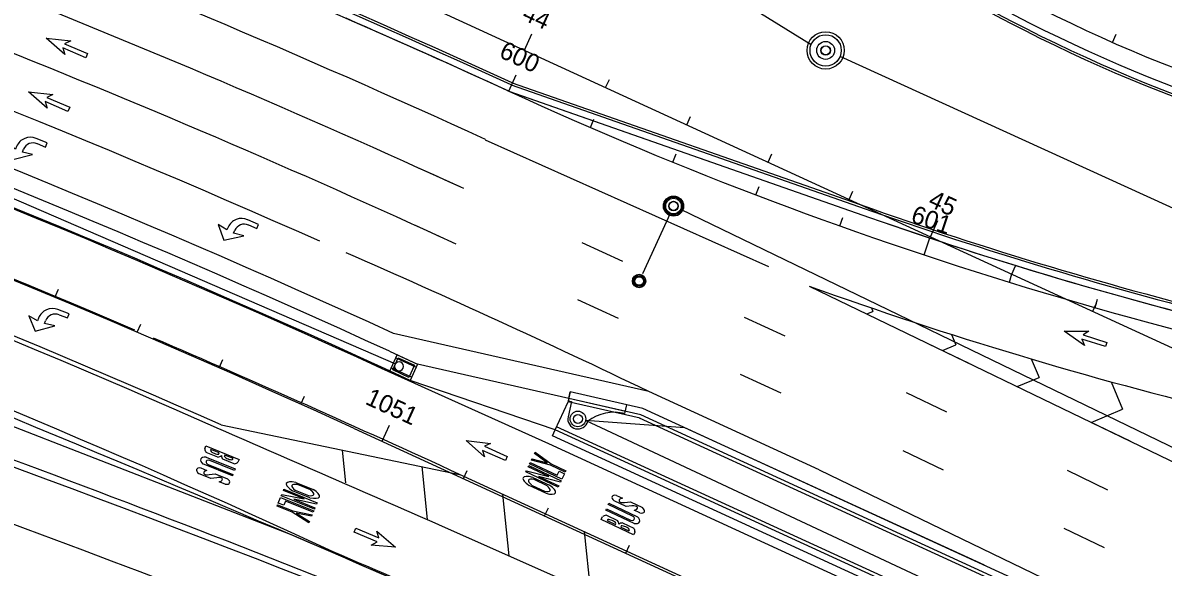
# Model space of a CAD drawing. Extents: x 468143 to 491361, y 1438528 to 1468730.
# Drawn here: x 487342.4 to 487597.7, y 1467252.2 to 1467373.9 of the extents above; entities that cross this region are included whole.
import ezdxf

# ---------------------------------------------------------------- set-up
doc = ezdxf.new("R2010")
doc.units = 0
doc.layers.add('Default', color=7, linetype='Continuous')
doc.layers.add('Xreference_dp', color=7, linetype='Continuous')

# ---------------------------------------------------------------- blocks, each defined once
blk = doc.blocks.new('POINT_DISPLAY')
at = {"layer": 'Default'}
blk.add_line((0, 0), (0, 0), dxfattribs=at)
blk = doc.blocks.new('InltCurb1_35')
at = {"layer": 'Default'}
for p, q in [((2.25, 2), (2.25, 5.5)), ((-10, 2), (-10, 0)), ((-10, 1.5), (3, 1.5)), ((3, 2), (2.25, 2)), ((3, 0), (3, 2))]:
    blk.add_line(p, q, dxfattribs=at)
for radius in [1.75, 1]:
    blk.add_circle((0, 5.5), radius, dxfattribs=at)
for centre, radius, start, end in [((0, 5.5), 2.25, 0, 180), ((-9.85, 12), 10, 269.1432, 319.4677)]:
    blk.add_arc(centre, radius, start, end, dxfattribs=at)
for p in [(0, 7.75), (-1.75, 5.5), (-1.75, 5.5), (-1.6, 6.2), (-1.22, 6.76), (-0.66, 7.12), (0, 7.25), (0, 7.25), (0, 5.5), (0, 5.5), (0.7, 7.1), (1.26, 6.72), (1.62, 6.16), (1.75, 5.5), (1.75, 5.5), (-1.62, 4.84), (-1.26, 4.28), (-0.7, 3.9), (0, 3.75), (0, 3.75), (0.66, 3.88), (1.22, 4.24), (1.6, 4.8), (0, 0), (0, 0)]:
    blk.add_blockref('POINT_DISPLAY', p, dxfattribs=at)
blk = doc.blocks.new('InltCurb7_40')
at = {"layer": 'Default'}
for p, q in [((2.5, 4), (-2.5, 4)), ((-2.5, 4), (-2.5, 0)), ((2.5, 3.25), (-2.5, 3.25)), ((2.5, 0), (2.5, 4)), ((-2.5, 0.75), (2.5, 0.75)), ((-2.5, 0), (2.5, 0))]:
    blk.add_line(p, q, dxfattribs=at)
blk.add_lwpolyline([(-2, 0.5), (2, 0.5), (2, 3.5), (-2, 3.5)], close=True, dxfattribs=at)
blk.add_circle((-1.04, 2.19), 1, dxfattribs=at)
for p in [(-2, 3.5), (0, 4), (0, 3.5), (0, 3.5), (2, 3.5), (-2, 2), (-2, 2), (-2, 0.5), (0, 2), (0, 2), (0, 0.5), (0, 0.5), (0, 0), (0, 0), (2, 2), (2, 2), (2, 0.5)]:
    blk.add_blockref('POINT_DISPLAY', p, dxfattribs=at)
blk = doc.blocks.new('MH2')
at = {"layer": 'Default'}
for p, q in [((-1.25, 0.03), (-1.05, 0.03)), ((-0.9, 0.87), (-0.76, 0.73)), ((-0.87, 0.9), (-0.73, 0.76)), ((-0.03, 1.25), (-0.03, 1.05)), ((0.03, 1.25), (0.03, 1.05)), ((0.87, 0.9), (0.73, 0.76)), ((0.9, 0.87), (0.76, 0.73)), ((1.05, 0.03), (1.25, 0.03)), ((-1.25, -0.03), (-1.05, -0.03)), ((-0.76, -0.73), (-0.9, -0.87)), ((-0.73, -0.76), (-0.87, -0.9)), ((-0.03, -1.05), (-0.03, -1.25)), ((0.03, -1.05), (0.03, -1.25)), ((0.73, -0.76), (0.87, -0.9)), ((0.76, -0.73), (0.9, -0.87)), ((1.05, -0.03), (1.25, -0.03))]:
    blk.add_line(p, q, dxfattribs=at)
for radius in [1.5, 1.25, 1.05, 1, 0.958]:
    blk.add_circle((0, 0), radius, dxfattribs=at)
for p in [(-1, 0), (-0.71, 0.71), (0, 1.5), (0, 1), (0, 0), (0, 0), (0, 0), (0.71, 0.71), (1, 0), (-0.71, -0.71), (0, -1), (0, -1.5), (0.71, -0.71)]:
    blk.add_blockref('POINT_DISPLAY', p, dxfattribs=at)
blk = doc.blocks.new('MHCover2')
at = {"layer": 'Default'}
for radius in [2, 1.06, 1]:
    blk.add_circle((0, 0), radius, dxfattribs=at)
for p in [(-2, 0), (-2, 0), (-1.83, 0.81), (-1.39, 1.43), (-0.75, 1.85), (0, 2.5), (0, 2), (0, 2), (0, 0), (0, 0), (0, 0), (0.81, 1.83), (1.43, 1.39), (1.85, 0.75), (2, 0), (2, 0), (-1.85, -0.75), (-1.43, -1.39), (-0.81, -1.83), (0, -2), (0, -2), (0, -2.5), (0.75, -1.85), (1.39, -1.43), (1.83, -0.81)]:
    blk.add_blockref('POINT_DISPLAY', p, dxfattribs=at)
blk = doc.blocks.new('JBottom70Dia')
at = {"layer": 'Default'}
for radius in [4.17, 3.5, 3.5]:
    blk.add_circle((0, 0), radius, dxfattribs=at)
for p in [(-1.32, 3.24), (0, 3.5), (0, 3.5), (0, 3.5), (1.41, 3.2), (-3.5, 0), (-3.5, 0), (-3.2, 1.41), (-2.44, 2.51), (0, 0), (0, 0), (0, 0), (2.51, 2.44), (3.24, 1.32), (-3.24, -1.32), (-2.51, -2.44), (2.44, -2.51), (3.2, -1.41), (3.5, 0), (3.5, 0), (-1.41, -3.2), (0, -3.5), (0, -3.5), (0, -3.5), (1.32, -3.24)]:
    blk.add_blockref('POINT_DISPLAY', p, dxfattribs=at)
blk = doc.blocks.new('PBottom35Dia')
at = {"layer": 'Default'}
for radius in [2.25, 1.75, 1.75]:
    blk.add_circle((0, 0), radius, dxfattribs=at)
for p in [(-1.75, 0), (-1.75, 0), (-1.6, 0.7), (-1.22, 1.26), (-0.66, 1.62), (0, 1.75), (0, 1.75), (0, 1.75), (0, 0), (0, 0), (0.7, 1.6), (1.26, 1.22), (1.62, 0.66), (1.75, 0), (1.75, 0), (-1.62, -0.66), (-1.26, -1.22), (-0.7, -1.6), (0, -1.75), (0, -1.75), (0, -1.75), (0.66, -1.62), (1.22, -1.26), (1.6, -0.7)]:
    blk.add_blockref('POINT_DISPLAY', p, dxfattribs=at)
blk = doc.blocks.new('DALeftTurn_1')
at = {"layer": 'Default'}
for points in [[(5.67, 3.17), (2, 0.5), (4.33, 0.83), (4.33, 0.17)], [(6, 0.17), (6, 0.83), (8.25, 0.5), (5.67, 3.17)], [(2, -2.17), (0, -2.17), (0, -3.17), (2.67, -3.17)]]:
    blk.add_lwpolyline(points, dxfattribs=at)
for centre, radius in [((2, 0.17), 2.33), ((2.67, 0.17), 3.33)]:
    blk.add_arc(centre, radius, 270, 0, dxfattribs=at)
blk = doc.blocks.new('DAMerge_2')
at = {"layer": 'Default'}
blk.add_lwpolyline([(0.71, -4.09), (0, -3.39), (3.95, 0.56), (2.42, 0.68), (7.31, 3.21), (4.77, -1.68), (4.66, -0.15), (0.71, -4.09)], dxfattribs=at)
blk = doc.blocks.new('BUS_7')
at = {"layer": 'Default'}
for p, q in [((0, 2.46), (0, 3.17)), ((0, 3.17), (8, 3.17)), ((3.33, 2.83), (1.33, 2.83)), ((1.33, 2.83), (1.33, 2.58)), ((3.33, 2.58), (3.33, 2.83)), ((6.67, 2.83), (4.67, 2.83)), ((4.67, 2.83), (4.67, 2.58)), ((6.67, 2.58), (6.67, 2.83)), ((8, 3.17), (8, 2.46)), ((3.38, 1.83), (0.62, 1.83)), ((0.97, 0.86), (8, 0.86)), ((8, 0.5), (2, 0.5)), ((7.38, 1.83), (4.62, 1.83)), ((8, 0.86), (8, 0.5)), ((0.8, -1.83), (2.26, -1.83)), ((8, -0.83), (0.89, -0.83)), ((2, -0.5), (8, -0.5)), ((3.08, -2.5), (4.23, -1.83)), ((4.93, -2.5), (3.77, -3.17)), ((4.23, -1.83), (7.2, -1.83)), ((8, -0.5), (8, -0.83)), ((3.77, -3.17), (0.8, -3.17)), ((7.2, -3.17), (5.74, -3.17))]:
    blk.add_line(p, q, dxfattribs=at)
for centre, major_axis, ratio, start_param, end_param in [((2.33, 2.83), (-1.17, 0), 0.428571, 0.5411, 2.600493), ((5.67, 2.83), (1.17, 0), 0.428571, 3.682692, 5.742086), ((2, 0), (2, 0), 0.5, 2.110653, 4.126703), ((2, 2.83), (-2.08, 0), 0.64, 0.283794, 0.848062), ((2, 0), (0.667, 0), 0.75, 1.570796, 4.712389), ((2, 2.83), (-2.08, 0), 0.64, 2.293531, 2.857799), ((6, 2.83), (2.08, 0), 0.64, 3.425387, 3.989655), ((6, 2.83), (2.08, 0), 0.64, 5.435123, 5.999391), ((2, -2.5), (-2, 0), 0.416667, 5.35589, 7.210481), ((2.67, -2.17), (-0.877, -0.48), 0.5, 4.914869, 8.056461), ((5.33, -2.83), (-0.869, -0.495), 0.5, 1.760499, 4.902092), ((6, -2.5), (2, 0), 0.416667, 5.35589, 7.210481)]:
    blk.add_ellipse(centre, major_axis=major_axis, ratio=ratio, start_param=start_param, end_param=end_param, dxfattribs=at)
blk = doc.blocks.new('BikeONLY_2')
at = {"layer": 'Default'}
for p, q in [((0.97, 1.83), (3.03, 1.83)), ((2.8, 1.67), (1.2, 1.67)), ((3.03, 0.83), (0.97, 0.83)), ((1.2, 1), (2.8, 1))]:
    blk.add_line(p, q, dxfattribs=at)
for points in [[(0, -0.17), (0, 0), (2.5, 0.46), (0, 0.46), (0, 0.62), (4, 0.62), (4, 0.46), (1.45, 0), (4, 0), (4, -0.17), (0, -0.17)], [(0.67, -1.04), (0, -1.04), (0, -0.37), (4, -0.37), (4, -0.54), (0.67, -0.54), (0.67, -1.04)], [(4, -1.83), (1.83, -1.42), (0, -1.42), (0, -1.25), (1.83, -1.25), (4, -0.83), (4, -1), (2.28, -1.33), (4, -1.66), (4, -1.83)]]:
    blk.add_lwpolyline(points, dxfattribs=at)
for major_axis, ratio, start_param, end_param in [((2, 0), 0.291667, 2.111896, 4.171289), ((1.33, 0), 0.3125, 2.214297, 4.068888), ((1.33, 0), 0.3125, 5.35589, 7.210481), ((2, 0), 0.291667, 5.253489, 7.312882)]:
    blk.add_ellipse((2, 1.33), major_axis=major_axis, ratio=ratio, start_param=start_param, end_param=end_param, dxfattribs=at)
blk = doc.blocks.new('DALeftTurn_4_1')
at = {"layer": 'Default'}
for points in [[(5.67, 3.17), (2, 0.5), (4.33, 0.83), (4.33, 0.17)], [(6, 0.17), (6, 0.83), (8.25, 0.5), (5.67, 3.17)], [(2, -2.17), (0, -2.17), (0, -3.17), (2.67, -3.17)]]:
    blk.add_lwpolyline(points, dxfattribs=at)
for centre, radius in [((2, 0.17), 2.33), ((2.67, 0.17), 3.33)]:
    blk.add_arc(centre, radius, 270, 0, dxfattribs=at)
blk = doc.blocks.new('DAMerge_6')
at = {"layer": 'Default'}
blk.add_lwpolyline([(0.71, -4.09), (0, -3.39), (3.95, 0.56), (2.42, 0.68), (7.31, 3.21), (4.77, -1.68), (4.66, -0.15), (0.71, -4.09)], dxfattribs=at)
blk = doc.blocks.new('BUS_8')
at = {"layer": 'Default'}
for p, q in [((0, 2.46), (0, 3.17)), ((0, 3.17), (8, 3.17)), ((3.33, 2.83), (1.33, 2.83)), ((1.33, 2.83), (1.33, 2.58)), ((3.33, 2.58), (3.33, 2.83)), ((6.67, 2.83), (4.67, 2.83)), ((4.67, 2.83), (4.67, 2.58)), ((6.67, 2.58), (6.67, 2.83)), ((8, 3.17), (8, 2.46)), ((3.38, 1.83), (0.62, 1.83)), ((0.97, 0.86), (8, 0.86)), ((8, 0.5), (2, 0.5)), ((7.38, 1.83), (4.62, 1.83)), ((8, 0.86), (8, 0.5)), ((0.8, -1.83), (2.26, -1.83)), ((8, -0.83), (0.89, -0.83)), ((2, -0.5), (8, -0.5)), ((3.08, -2.5), (4.23, -1.83)), ((4.93, -2.5), (3.77, -3.17)), ((4.23, -1.83), (7.2, -1.83)), ((8, -0.5), (8, -0.83)), ((3.77, -3.17), (0.8, -3.17)), ((7.2, -3.17), (5.74, -3.17))]:
    blk.add_line(p, q, dxfattribs=at)
for centre, major_axis, ratio, start_param, end_param in [((2.33, 2.83), (-1.17, 0), 0.428571, 0.5411, 2.600493), ((5.67, 2.83), (1.17, 0), 0.428571, 3.682692, 5.742086), ((2, 0), (2, 0), 0.5, 2.110653, 4.126703), ((2, 2.83), (-2.08, 0), 0.64, 0.283794, 0.848062), ((2, 0), (0.667, 0), 0.75, 1.570796, 4.712389), ((2, 2.83), (-2.08, 0), 0.64, 2.293531, 2.857799), ((6, 2.83), (2.08, 0), 0.64, 3.425387, 3.989655), ((6, 2.83), (2.08, 0), 0.64, 5.435123, 5.999391), ((2, -2.5), (-2, 0), 0.416667, 5.35589, 7.210481), ((2.67, -2.17), (-0.877, -0.48), 0.5, 4.914869, 8.056461), ((5.33, -2.83), (-0.869, -0.495), 0.5, 1.760499, 4.902092), ((6, -2.5), (2, 0), 0.416667, 5.35589, 7.210481)]:
    blk.add_ellipse(centre, major_axis=major_axis, ratio=ratio, start_param=start_param, end_param=end_param, dxfattribs=at)
blk = doc.blocks.new('BikeONLY_4')
at = {"layer": 'Default'}
for p, q in [((0.97, 1.83), (3.03, 1.83)), ((2.8, 1.67), (1.2, 1.67)), ((3.03, 0.83), (0.97, 0.83)), ((1.2, 1), (2.8, 1))]:
    blk.add_line(p, q, dxfattribs=at)
for points in [[(0, -0.17), (0, 0), (2.5, 0.46), (0, 0.46), (0, 0.62), (4, 0.62), (4, 0.46), (1.45, 0), (4, 0), (4, -0.17), (0, -0.17)], [(0.67, -1.04), (0, -1.04), (0, -0.37), (4, -0.37), (4, -0.54), (0.67, -0.54), (0.67, -1.04)], [(4, -1.83), (1.83, -1.42), (0, -1.42), (0, -1.25), (1.83, -1.25), (4, -0.83), (4, -1), (2.28, -1.33), (4, -1.66), (4, -1.83)]]:
    blk.add_lwpolyline(points, dxfattribs=at)
for major_axis, ratio, start_param, end_param in [((2, 0), 0.291667, 2.111896, 4.171289), ((1.33, 0), 0.3125, 2.214297, 4.068888), ((1.33, 0), 0.3125, 5.35589, 7.210481), ((2, 0), 0.291667, 5.253489, 7.312882)]:
    blk.add_ellipse((2, 1.33), major_axis=major_axis, ratio=ratio, start_param=start_param, end_param=end_param, dxfattribs=at)
blk = doc.blocks.new('DALeftTurn_5')
at = {"layer": 'Default'}
for points in [[(5.67, 3.17), (2, 0.5), (4.33, 0.83), (4.33, 0.17)], [(6, 0.17), (6, 0.83), (8.25, 0.5), (5.67, 3.17)], [(2, -2.17), (0, -2.17), (0, -3.17), (2.67, -3.17)]]:
    blk.add_lwpolyline(points, dxfattribs=at)
for centre, radius in [((2, 0.17), 2.33), ((2.67, 0.17), 3.33)]:
    blk.add_arc(centre, radius, 270, 0, dxfattribs=at)

msp = doc.modelspace()

# ---------------------------------------------------------------- linework, layer by layer
at = {"layer": 'Xreference_dp'}
for p, q in [((487374.27, 1467458.66), (487518.88, 1467369.05)), ((487372.29, 1467405.61), (488386.67, 1466939.92)), ((487454.7, 1467367.78), (487456.36, 1467371.41)), ((487586.33, 1467369.52), (487587.14, 1467371.35)), ((487846.39, 1467219.77), (487525.36, 1467366.39)), ((487451.19, 1467358.61), (487452.86, 1467362.25)), ((487451.75, 1467360.01), (487532.44, 1467331.79)), ((487451.94, 1467360.47), (487532.6, 1467332.26)), ((487472.87, 1467359.43), (487473.71, 1467361.25)), ((487451.01, 1467358.68), (487531.94, 1467330.37)), ((487451.19, 1467358.61), (487531.94, 1467330.37)), ((487469.46, 1467350.48), (487470.26, 1467352.31)), ((487491.05, 1467351.09), (487491.88, 1467352.91)), ((487509.43, 1467319.35), (487445.97, 1467347.67)), ((487487.9, 1467342.74), (487488.66, 1467344.59)), ((487509.22, 1467342.74), (487510.06, 1467344.56)), ((487440.33, 1467337.18), (487431.21, 1467341.29)), ((487506.51, 1467335.41), (487507.22, 1467337.28)), ((487339.35, 1467335.08), (487425.86, 1467297.62)), ((487527.4, 1467334.4), (487528.23, 1467336.22)), ((487489.67, 1467332.21), (487611.95, 1467273.08)), ((487481.17, 1467317.86), (487487.36, 1467331.3)), ((487525.27, 1467328.48), (487525.95, 1467330.37)), ((487545.58, 1467326.06), (487547.24, 1467329.69)), ((487439.41, 1467324.41), (487430.3, 1467328.54)), ((487476.7, 1467320.52), (487467.61, 1467324.69)), ((487544.18, 1467321.97), (487545.44, 1467325.77)), ((487563.75, 1467317.71), (487564.59, 1467319.53)), ((487563.23, 1467315.87), (487563.82, 1467317.78)), ((487349.63, 1467312.48), (487350.4, 1467314.32)), ((487518.46, 1467314.99), (487606.04, 1467272.69)), ((487475.77, 1467307.74), (487466.68, 1467311.91)), ((487582.41, 1467310.19), (487582.95, 1467312.11)), ((487531.33, 1467308.78), (487532.7, 1467309.35)), ((487532.38, 1467310.12), (487532.7, 1467309.35)), ((487581.93, 1467309.37), (487582.76, 1467311.18)), ((487368.05, 1467304.69), (487368.84, 1467306.53)), ((487513.06, 1467303.85), (487503.97, 1467308.01)), ((487482.52, 1467291.44), (487425.42, 1467304.43)), ((487550.26, 1467304.22), (487551.25, 1467301.87)), ((487554.25, 1467297.72), (487545.24, 1467302.06)), ((487548.24, 1467300.61), (487551.25, 1467301.87)), ((487386.4, 1467296.73), (487387.2, 1467298.56)), ((487424.5, 1467300.45), (487430.78, 1467297.57)), ((487568.14, 1467298.71), (487569.88, 1467294.58)), ((487460.14, 1467279.7), (487422.73, 1467296.58)), ((487464.64, 1467289.87), (487430.78, 1467297.57)), ((487461.6, 1467282.88), (487429.11, 1467293.92)), ((487512.13, 1467291.07), (487503.04, 1467295.24)), ((487564.98, 1467292.53), (487569.88, 1467294.58)), ((487586.03, 1467293.6), (487588.59, 1467287.5)), ((487464.64, 1467289.87), (487464.97, 1467291.33)), ((487481.23, 1467287.63), (487464.97, 1467291.33)), ((487520.69, 1467273.94), (487482.52, 1467291.44)), ((487549.24, 1467286.81), (487540.24, 1467291.15)), ((487404.67, 1467288.59), (487405.49, 1467290.42)), ((487461.6, 1467282.88), (487464.47, 1467289.14)), ((487464.64, 1467289.87), (487464.47, 1467289.14)), ((487480.58, 1467285.47), (487464.47, 1467289.14)), ((487480.75, 1467286.21), (487464.64, 1467289.87)), ((487402.34, 1467259.43), (487330.59, 1467287.36)), ((487896.93, 1467095.38), (487480.75, 1467286.21)), ((487897.55, 1467096.74), (487481.23, 1467287.63)), ((487581.52, 1467284.53), (487588.59, 1467287.5)), ((487386.85, 1467283.96), (487440.18, 1467272.9)), ((487422.86, 1467280.3), (487424.53, 1467283.93)), ((487892.66, 1467086.06), (487461.92, 1467283.57)), ((487552.54, 1467245.59), (487468.38, 1467284.92)), ((487490.57, 1467283.35), (487468.38, 1467284.92)), ((487896.62, 1467094.69), (487480.46, 1467285.51)), ((487557.67, 1467252.59), (487490.57, 1467283.35)), ((487590.26, 1467280.32), (487581.26, 1467284.67)), ((487416.58, 1467283.18), (488348.99, 1466855.64)), ((487460.98, 1467281.52), (487461.6, 1467282.88)), ((487891.72, 1467084.01), (487460.98, 1467281.52)), ((487892.34, 1467085.38), (487461.6, 1467282.88)), ((487413.91, 1467278.35), (487414.69, 1467270.98)), ((487890.89, 1467082.19), (487460.14, 1467279.7)), ((487548.49, 1467273.84), (487539.49, 1467278.19)), ((487431.72, 1467274.66), (487432.97, 1467262.85)), ((487441.04, 1467271.96), (487441.88, 1467273.78)), ((487520.69, 1467273.94), (487700.82, 1467186.95)), ((487585.26, 1467269.41), (487576.26, 1467273.76)), ((487884.84, 1467069.01), (487440.18, 1467272.9)), ((487449.79, 1467268.5), (487451.24, 1467254.72)), ((487459.22, 1467263.62), (487460.06, 1467265.44)), ((487435.5, 1467261.72), (487882.12, 1467063.09)), ((487584.51, 1467256.44), (487575.51, 1467260.79)), ((487468.09, 1467260.11), (487469.52, 1467246.59)), ((487477.4, 1467255.29), (487478.24, 1467257.11))]:
    msp.add_line(p, q, dxfattribs=at)
for centre, radius, start, end in [((486541.29, 1465374.28), 2185, 65.36901, 75.94924), ((486541.29, 1465374.28), 2184.5, 65.36842, 75.94131), ((486541.29, 1465374.28), 2183, 65.36658, 75.94131), ((486541.29, 1465374.28), 2100, 65.36712, 99.90595), ((487722.14, 1467677.97), 318.03, 226.2873, 264.1733), ((486541.29, 1465374.28), 2135, 66.02244, 75.79826), ((487722.14, 1467677.97), 337.03, 223.5592, 264.1733), ((487722.14, 1467677.97), 337.03, 223.5591, 264.1733), ((487722.14, 1467677.97), 322.03, 226.2873, 264.1733), ((487722.14, 1467677.97), 341.03, 224.4359, 264.1733), ((487722.14, 1467677.97), 343.03, 224.4359, 264.1733), ((487722.14, 1467677.97), 342.53, 224.4359, 264.1733), ((486541.29, 1465374.28), 2123, 65.38933, 75.79741), ((486541.29, 1465374.28), 2119, 65.36712, 75.79712), ((486541.29, 1465374.28), 2114.75, 65.36712, 75.79712), ((486541.29, 1465374.28), 2115, 65.17986, 75.79712), ((486541.29, 1465374.28), 2159, 65.36712, 71.6749), ((486541.29, 1465374.28), 2147, 65.36712, 71.66221), ((486541.29, 1465374.28), 2100.25, 66.83331, 75.79712), ((487722.14, 1467677.97), 316.49, 241.1368, 264.1733), ((486541.29, 1465374.28), 2088.5, 66.11758, 75.79731), ((486541.29, 1465374.28), 2171, 65.37161, 68.95975), ((486541.29, 1465374.28), 2087.5, 66.11758, 75.79732), ((486541.2, 1465374.31), 2183, 65.36908, 66.4109), ((486541.29, 1465374.28), 2073, 65.16596, 74.37116), ((487833.29, 1468191.92), 916.73, 245.36712, 261.35759), ((486023.86, 1463709.86), 3800, 66.68453, 72.73052), ((487833.29, 1468191.92), 911.23, 250.72144, 256.32908), ((487833.29, 1468191.92), 910.73, 250.72144, 256.32911), ((487833.29, 1468191.92), 912.73, 250.72144, 256.32899), ((487833.29, 1468191.92), 912.73, 250.72144, 256.27613), ((486023.86, 1463709.86), 3788, 66.09315, 72.73052), ((486559.16, 1465365.93), 2135.46, 64.38041, 66.37938), ((486023.86, 1463709.86), 3776, 66.11865, 72.73052), ((487833.29, 1468191.92), 931.73, 250.25095, 256.32899), ((486148.08, 1464462.24), 3093.44, 65.31102, 66.69894), ((485288.17, 1462318.17), 5374.55, 66.0273, 67.70446), ((486236.65, 1464294.69), 3179.16, 66.0273, 70.00614), ((529734.67, 1564625.99), 106155.64, 246.4888366, 246.5178272), ((485288.17, 1462318.17), 5374.55, 66.41645, 66.83583), ((485288.17, 1462318.17), 5374.8, 66.0273, 66.72566)]:
    msp.add_arc(centre, radius, start, end, dxfattribs=at)

# ---------------------------------------------------------------- block references
for name, p, rotation in [('DAMerge_2', (487353.38, 1467364.83), 111.66813866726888), ('DAMerge_6', (487353.38, 1467364.83), 111.66813866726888), ('JBottom70Dia', (487522.12, 1467367.72), 170.05563816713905), ('MHCover2', (487522.12, 1467367.72), 75.04782274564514), ('DAMerge_2', (487349.4, 1467352.84), 111.66813866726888), ('DAMerge_6', (487349.4, 1467352.84), 111.66813866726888), ('DALeftTurn_4_1', (487346.67, 1467344.1), 157.38505044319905), ('DALeftTurn_5', (487346.67, 1467344.1), 157.38505044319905), ('MHCover2', (487488.07, 1467332.91), 66.40871719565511), ('PBottom35Dia', (487488.07, 1467332.91), 66.40871719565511), ('DALeftTurn_1', (487393.92, 1467325.88), 155.9961894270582), ('MH2', (487480.38, 1467316.15), 65.36711924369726), ('DALeftTurn_1', (487351.65, 1467305.87), 158.8472745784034), ('DAMerge_2', (487581.74, 1467299.92), 117.37418667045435), ('DAMerge_6', (487581.74, 1467299.92), 117.37418667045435), ('InltCurb1_35', (487467.89, 1467290.67), 167.19116754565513), ('DAMerge_2', (487447.27, 1467274.78), 111.07491842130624), ('DAMerge_6', (487447.27, 1467274.78), 111.07491842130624), ('BUS_7', (487382.25, 1467276.33), -22.066060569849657), ('BUS_8', (487382.25, 1467276.33), -22.066060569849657), ('BUS_7', (487480.5, 1467262.28), 154.82725300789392), ('BUS_8', (487480.5, 1467262.28), 154.82725300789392), ('DAMerge_2', (487420.12, 1467262.16), -67.66514950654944), ('DAMerge_6', (487420.12, 1467262.16), -67.66514950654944)]:
    msp.add_blockref(name, p, dxfattribs=dict(at, rotation=rotation))
at = {"layer": 'Xreference_dp', "yscale": -0.9999999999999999, "rotation": -24.632880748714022}
msp.add_blockref('InltCurb7_40', (487428.51, 1467298.61), dxfattribs=at)
at = {"layer": 'Xreference_dp'}
for name, p, xscale, yscale, rotation in [('BikeONLY_2', (487462.79, 1467271.16), 2, 2, 154.82725300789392), ('BikeONLY_4', (487462.79, 1467271.16), 2, 2, 154.82725300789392), ('BikeONLY_2', (487400.41, 1467268.43), 1.9999999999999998, 2.0000000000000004, -22.066060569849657), ('BikeONLY_4', (487400.41, 1467268.43), 1.9999999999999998, 2.0000000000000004, -22.066060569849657)]:
    msp.add_blockref(name, p, dxfattribs=dict(at, xscale=xscale, yscale=yscale, rotation=rotation))

# ---------------------------------------------------------------- texts
for s, rotation, p in [('44', 335.3408, (487453.93, 1467374.73)), ('600', 335.3671, (487448.8, 1467366.31)), ('45', 335.3408, (487544.82, 1467333.01)), ('601', 341.6171, (487540.96, 1467329.36)), ('1051', 335.3671, (487418.84, 1467288.74))]:
    msp.add_text(s, height=4, rotation=rotation, dxfattribs=at).set_placement(p)

doc.saveas('drawing.dxf')
